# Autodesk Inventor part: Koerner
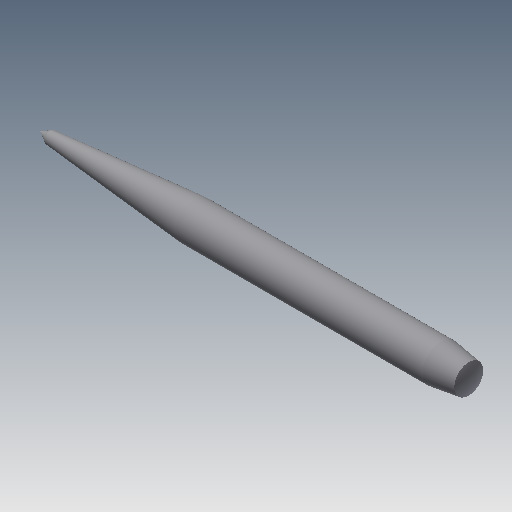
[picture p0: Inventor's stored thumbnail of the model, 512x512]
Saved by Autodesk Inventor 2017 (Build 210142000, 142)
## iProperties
Created: 2015-06
Part Number: Koerner
Material: Generisch
Document SubType Name: Modeling
Designer: e_krauts
Density: 1 g/cm^3
Appearance: Vorgabe
Author: e_krauts
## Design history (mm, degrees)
sketch "Skizze1"
  geometry: L1 (71.12, 0)-(-75, 0) reference; L2 (-30.05, 2.366)-(-25.536, 3); L3 (-25.536, 3)-(14.464, 3); L4 (14.464, 3)-(37.805, 0.958); L5 (37.805, 0.958)-(39.464, 0); A1 r 6 centre (-24.536, 0) between (-30.05, 2.366) and (-30.536, 0); 1 further point
  constraints: 10 end point, 3 point on line, 2 horizontal, 2 point on circle, 1 centre point, 1 parallel
  dimensions: "d5" = 6 diameter of L3 L1; "d6" = 6 radius of A1; "d7" = 5 horizontal distance of L2.end A1.end; "d8" = 188 deg dimension on L2 L3; "d11" = 25 horizontal distance of L5.end L3.end; "d12" = 30 deg angle of L5 L1; "d14" = 5 deg angle of L3 L4; "d15" = 70 distance of L5.end A1.end
revolve "Umdrehung1" sketch "Skizze1" stored, may be unused: angle "d16" = 90 deg
node "Volumenkörper1"
